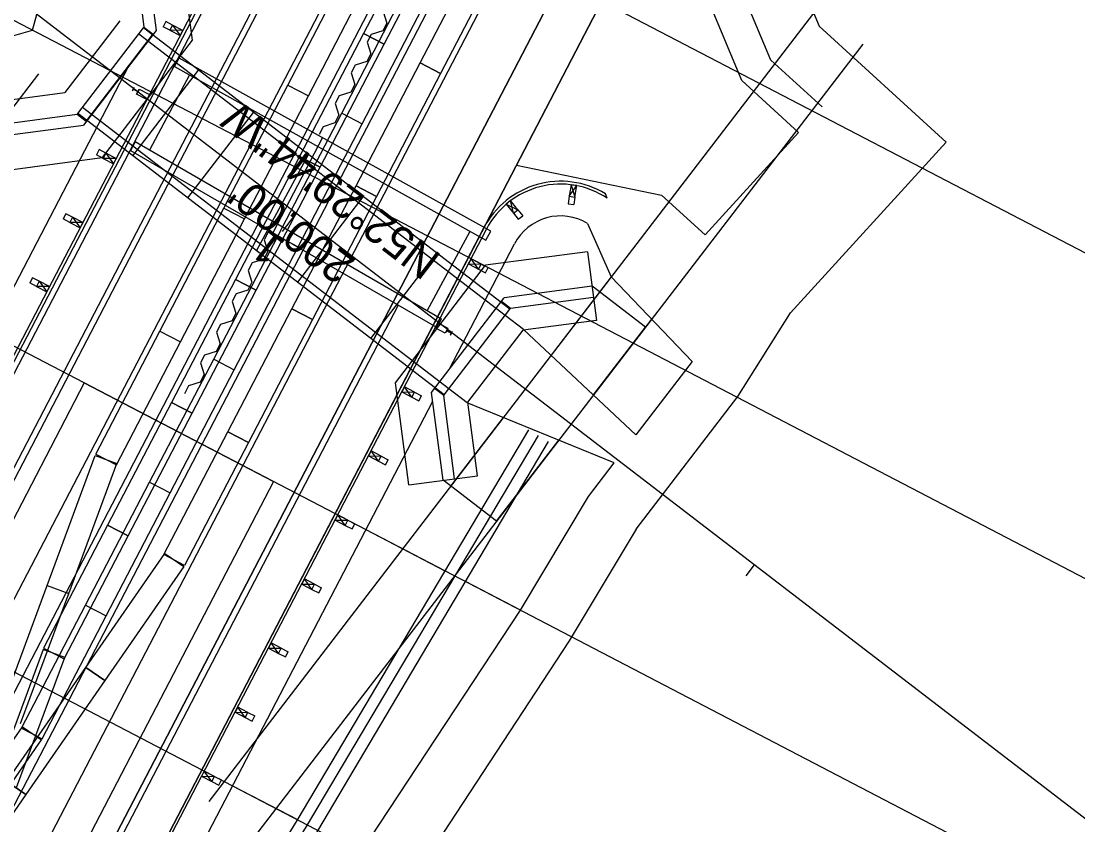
# Model space of a CAD drawing. Extents: x 2034057 to 2035954, y 247386 to 249135.
# Drawn here: x 2034212.3 to 2034303.8, y 247789 to 247858.5 of the extents above; entities that cross this region are included whole.
import ezdxf

# ---------------------------------------------------------------- set-up
doc = ezdxf.new("R2010")
doc.units = 0
for name, color, linetype in [('_CIVIL_CONSTRUCTION', 7, 'Continuous'), ('Default', 7, 'Continuous'), ('DR_X_Storm_Sewer', 7, 'Continuous'), ('DV_X_Property_Line', 7, 'Continuous'), ('GE_X_Alignment_1000_Curve_Data', 7, 'Continuous'), ('GE_X_Alignment_1000_Stations', 7, 'Continuous'), ('HY_X_Water_Edge', 7, 'Continuous'), ('PV_X_Driveway', 7, 'Continuous'), ('RD_X_Fence', 7, 'Continuous'), ('RD_X_GR_Lt', 7, 'Continuous'), ('RS_Raster1', 7, 'Continuous'), ('RW_X_CL_100_Cardinal_Points', 7, 'Continuous'), ('RW_X_Esmt_SH', 7, 'Continuous'), ('SC_Scratch1', 7, 'Continuous'), ('SN_X_Public', 7, 'Continuous'), ('SN_X_Text', 7, 'Continuous'), ('SV_Control_Point', 7, 'Continuous'), ('SV_P_Mon_Cells_Set', 7, 'Continuous'), ('SV_X_Break_Lines', 7, 'Continuous'), ('SV_X_Top_of_Bank', 7, 'Continuous'), ('UT_X_Telecom', 7, 'Continuous'), ('VG_X_Text', 7, 'Continuous'), ('XS_X_Ground_Line', 7, 'Continuous')]:
    doc.layers.add(name, color=color, linetype=linetype)

msp = doc.modelspace()

# ---------------------------------------------------------------- linework, layer by layer
at = {"layer": '_CIVIL_CONSTRUCTION'}
for p, q in [((2034315.483, 247781.011), (2034156.822, 247902.775)), ((2034281.239, 247859.578), (2034228.588, 247790.974)), ((2034285.205, 247856.534), (2034232.555, 247787.93))]:
    msp.add_line(p, q, dxfattribs=at)
at = {"layer": 'Default'}
for p, q in [((2034160.613, 247913.346), (2034338.015, 247820.997)), ((2034149.071, 247891.179), (2034326.466, 247798.816)), ((2034137.526, 247869.005), (2034314.921, 247776.641)), ((2034125.98, 247846.83), (2034303.375, 247754.467))]:
    msp.add_line(p, q, dxfattribs=at)
at = {"layer": 'DR_X_Storm_Sewer'}
for p, q in [((2034277.243, 247855.142), (2034271.022, 247870.084)), ((2034277.243, 247855.142), (2034281.68, 247851.086)), ((2034221.609, 247854.561), (2034190.6, 247795.005)), ((2034210.536, 247849.577), (2034213.884, 247853.94)), ((2034261.377, 247841.011), (2034263.431, 247836.375)), ((2034249.396, 247828.353), (2034255.062, 247839.235)), ((2034263.431, 247836.375), (2034258.225, 247829.592)), ((2034270.426, 247829.065), (2034263.431, 247836.375)), ((2034266.929, 247832.72), (2034261.892, 247826.156)), ((2034270.426, 247829.065), (2034265.558, 247822.721)), ((2034208.787, 247750.357), (2034247.981, 247825.635)), ((2034249.631, 247818.393), (2034254.091, 247824.205)), ((2034261.452, 247817.371), (2034263.69, 247820.287)), ((2034242.189, 247814.51), (2034249.026, 247810.95)), ((2034255.564, 247807.546), (2034250.803, 247810.025)), ((2034230.643, 247792.336), (2034236.256, 247789.414))]:
    msp.add_line(p, q, dxfattribs=at)
for points in [[(2034256.26, 247823.151), (2034236.288, 247789.466), (2034223.216, 247768.065), (2034211.274, 247746.04), (2034200.52, 247723.551), (2034200.47, 247723.489)], [(2034257.98, 247822.131), (2034238.002, 247788.435), (2034224.95, 247767.067), (2034213.056, 247745.131), (2034202.261, 247722.557)], [(2034228.624, 247765.202), (2034241.766, 247786.545), (2034255.564, 247807.546), (2034261.452, 247817.371)]]:
    msp.add_lwpolyline(points, dxfattribs=at)
msp.add_arc((2034259.053, 247837.157), 4.5, 58.91768, 152.49557, dxfattribs=at)
at = {"layer": 'DV_X_Property_Line'}
for p, q in [((2034235.313, 247874.384), (2034186.854, 247781.313)), ((2034262.587, 247860.183), (2034214.128, 247767.112))]:
    msp.add_line(p, q, dxfattribs=at)
at = {"layer": 'GE_X_Alignment_1000_Curve_Data'}
for p, q in [((2034236.152, 247841.893), (2034234.935, 247840.306)), ((2034275.818, 247811.452), (2034275.087, 247810.5))]:
    msp.add_line(p, q, dxfattribs=at)
at = {"layer": 'HY_X_Water_Edge'}
for p, q in [((2034266.395, 247832.024), (2034261.77, 247835.574)), ((2034261.892, 247826.156), (2034266.395, 247832.024)), ((2034253.508, 247815.232), (2034258.891, 247822.246)), ((2034253.508, 247815.232), (2034248.883, 247818.782))]:
    msp.add_line(p, q, dxfattribs=at)
at = {"layer": 'PV_X_Driveway'}
for p, q in [((2034183.71, 247766.074), (2034239.082, 247872.422)), ((2034247.065, 247868.265), (2034191.693, 247761.917))]:
    msp.add_line(p, q, dxfattribs=at)
for points in [[(2034243.772, 247856.528), (2034249.314, 247867.172), (2034247.54, 247868.095), (2034241.998, 247857.452)], [(2034238.231, 247845.884), (2034243.772, 247856.528), (2034241.998, 247857.452), (2034236.457, 247846.808)], [(2034232.689, 247835.241), (2034238.231, 247845.884), (2034236.457, 247846.808), (2034230.915, 247836.164)], [(2034227.147, 247824.597), (2034232.689, 247835.241), (2034230.915, 247836.164), (2034225.373, 247825.521)], [(2034221.605, 247813.953), (2034227.147, 247824.597), (2034225.373, 247825.521), (2034219.831, 247814.877)], [(2034216.063, 247803.31), (2034221.605, 247813.953), (2034219.831, 247814.877), (2034214.289, 247804.233)], [(2034211.946, 247792.171), (2034216.114, 247803.424), (2034214.239, 247804.119), (2034210.071, 247792.866)]]:
    msp.add_lwpolyline(points, close=True, dxfattribs=at)
at = {"layer": 'RD_X_Fence'}
for p, q in [((2034243.686, 247859.362), (2034244.006, 247858.351)), ((2034243.661, 247857.685), (2034242.65, 247857.365)), ((2034244.006, 247858.351), (2034243.661, 247857.685)), ((2034242.65, 247857.365), (2034242.304, 247856.7)), ((2034242.304, 247856.7), (2034242.624, 247855.689)), ((2034242.279, 247855.023), (2034241.267, 247854.703)), ((2034242.624, 247855.689), (2034242.279, 247855.023)), ((2034241.267, 247854.703), (2034240.922, 247854.037)), ((2034240.922, 247854.037), (2034241.242, 247853.026)), ((2034240.896, 247852.36), (2034239.885, 247852.04)), ((2034241.242, 247853.026), (2034240.896, 247852.36)), ((2034239.885, 247852.04), (2034239.54, 247851.375)), ((2034239.54, 247851.375), (2034239.86, 247850.363)), ((2034239.86, 247850.363), (2034239.514, 247849.698)), ((2034239.514, 247849.698), (2034238.503, 247849.378)), ((2034238.503, 247849.378), (2034238.157, 247848.712)), ((2034233.736, 247840.248), (2034233.391, 247839.582)), ((2034233.391, 247839.582), (2034233.711, 247838.571)), ((2034233.711, 247838.571), (2034233.365, 247837.906)), ((2034232.354, 247837.586), (2034232.009, 247836.92)), ((2034233.365, 247837.906), (2034232.354, 247837.586)), ((2034232.009, 247836.92), (2034232.329, 247835.909)), ((2034232.329, 247835.909), (2034231.983, 247835.243)), ((2034230.972, 247834.923), (2034230.626, 247834.257)), ((2034231.983, 247835.243), (2034230.972, 247834.923)), ((2034230.626, 247834.257), (2034230.946, 247833.246)), ((2034230.946, 247833.246), (2034230.601, 247832.58)), ((2034229.59, 247832.26), (2034229.244, 247831.595)), ((2034230.601, 247832.58), (2034229.59, 247832.26)), ((2034229.244, 247831.595), (2034229.564, 247830.583)), ((2034229.564, 247830.583), (2034229.219, 247829.918)), ((2034228.207, 247829.598), (2034227.862, 247828.932)), ((2034229.219, 247829.918), (2034228.207, 247829.598)), ((2034227.862, 247828.932), (2034228.182, 247827.921)), ((2034228.182, 247827.921), (2034227.836, 247827.255)), ((2034226.825, 247826.935), (2034226.48, 247826.269)), ((2034227.836, 247827.255), (2034226.825, 247826.935))]:
    msp.add_line(p, q, dxfattribs=at)
at = {"layer": 'RD_X_GR_Lt'}
for p, q in [((2034204.76, 247768.608), (2034254.604, 247864.34)), ((2034212.743, 247764.451), (2034262.587, 247860.183))]:
    msp.add_line(p, q, dxfattribs=at)
for points in [[(2034254.193, 247864.632), (2034248.651, 247853.988), (2034246.877, 247854.912), (2034252.419, 247865.555)], [(2034248.651, 247853.988), (2034243.109, 247843.344), (2034241.335, 247844.268), (2034246.877, 247854.912)], [(2034243.109, 247843.344), (2034237.567, 247832.701), (2034235.793, 247833.624), (2034241.335, 247844.268)], [(2034237.567, 247832.701), (2034232.025, 247822.057), (2034230.251, 247822.981), (2034235.793, 247833.624)], [(2034232.025, 247822.057), (2034226.484, 247811.413), (2034224.71, 247812.337), (2034230.251, 247822.981)], [(2034226.419, 247811.306), (2034219.59, 247801.439), (2034217.945, 247802.577), (2034224.774, 247812.444)], [(2034219.59, 247801.439), (2034212.761, 247791.571), (2034211.117, 247792.709), (2034217.945, 247802.577)], [(2034212.761, 247791.571), (2034205.932, 247781.704), (2034204.288, 247782.842), (2034211.117, 247792.709)]]:
    msp.add_lwpolyline(points, close=True, dxfattribs=at)
at = {"layer": 'RS_Raster1'}
for p, q in [((2034188.682, 247783.743), (2034235.756, 247874.153)), ((2034243.739, 247869.997), (2034196.665, 247779.587)), ((2034235.44, 247852.975), (2034240.981, 247863.618)), ((2034237.214, 247852.051), (2034242.755, 247862.695)), ((2034229.898, 247842.331), (2034235.44, 247852.975)), ((2034235.44, 247852.975), (2034237.214, 247852.051)), ((2034235.44, 247852.975), (2034237.214, 247852.051)), ((2034231.672, 247841.407), (2034237.214, 247852.051)), ((2034224.356, 247831.687), (2034229.898, 247842.331)), ((2034229.898, 247842.331), (2034231.672, 247841.407)), ((2034229.898, 247842.331), (2034231.672, 247841.407)), ((2034226.13, 247830.764), (2034231.672, 247841.407)), ((2034218.814, 247821.044), (2034224.356, 247831.687)), ((2034224.356, 247831.687), (2034226.13, 247830.764)), ((2034224.356, 247831.687), (2034226.13, 247830.764)), ((2034220.588, 247820.12), (2034226.13, 247830.764)), ((2034214.596, 247809.676), (2034218.763, 247820.929)), ((2034216.471, 247808.982), (2034220.639, 247820.234)), ((2034218.763, 247820.929), (2034220.639, 247820.234)), ((2034218.814, 247821.044), (2034220.588, 247820.12)), ((2034210.428, 247798.423), (2034214.596, 247809.676)), ((2034214.596, 247809.676), (2034216.471, 247808.982)), ((2034214.596, 247809.676), (2034216.471, 247808.982)), ((2034212.303, 247797.729), (2034216.471, 247808.982))]:
    msp.add_line(p, q, dxfattribs=at)
at = {"layer": 'RW_X_Esmt_SH'}
for p, q in [((2034239.526, 247872.191), (2034170.285, 247739.206)), ((2034259.039, 247862.031), (2034189.798, 247729.046)), ((2034217.797, 247827.21), (2034171.615, 247738.513)), ((2034217.797, 247827.21), (2034234.206, 247818.667)), ((2034234.206, 247818.667), (2034188.024, 247729.969))]:
    msp.add_line(p, q, dxfattribs=at)
at = {"layer": 'SC_Scratch1'}
for p, q in [((2034251.056, 247866.187), (2034192.77, 247754.241)), ((2034200.753, 247750.085), (2034259.039, 247862.031)), ((2034240.096, 247850.55), (2034245.638, 247861.194)), ((2034241.87, 247849.627), (2034247.412, 247860.27)), ((2034234.554, 247839.906), (2034240.096, 247850.55)), ((2034240.096, 247850.55), (2034241.87, 247849.627)), ((2034240.096, 247850.55), (2034241.87, 247849.627)), ((2034236.328, 247838.983), (2034241.87, 247849.627)), ((2034229.013, 247829.263), (2034234.554, 247839.906)), ((2034234.554, 247839.906), (2034236.328, 247838.983)), ((2034234.554, 247839.906), (2034236.328, 247838.983)), ((2034230.787, 247828.339), (2034236.328, 247838.983)), ((2034223.471, 247818.619), (2034229.013, 247829.263)), ((2034229.013, 247829.263), (2034230.787, 247828.339)), ((2034229.013, 247829.263), (2034230.787, 247828.339)), ((2034225.245, 247817.695), (2034230.787, 247828.339)), ((2034217.929, 247807.975), (2034223.471, 247818.619)), ((2034223.471, 247818.619), (2034225.245, 247817.695)), ((2034223.471, 247818.619), (2034225.245, 247817.695)), ((2034219.703, 247807.052), (2034225.245, 247817.695)), ((2034212.387, 247797.332), (2034217.929, 247807.975)), ((2034217.929, 247807.975), (2034219.703, 247807.052)), ((2034217.929, 247807.975), (2034219.703, 247807.052)), ((2034214.161, 247796.408), (2034219.703, 247807.052)), ((2034205.623, 247787.571), (2034212.452, 247797.439)), ((2034212.387, 247797.332), (2034214.161, 247796.408)), ((2034212.452, 247797.439), (2034214.096, 247796.301)), ((2034207.268, 247786.433), (2034214.096, 247796.301))]:
    msp.add_line(p, q, dxfattribs=at)
at = {"layer": 'SN_X_Public'}
msp.add_line((2034244.977, 247833.939), (2034190.242, 247728.815), dxfattribs=at)
at = {"layer": 'SN_X_Text'}
msp.add_line((2034194.19, 247852.248), (2034213.315, 247857.73), dxfattribs=at)
for points in [[(2034213.315, 247857.73), (2034220.149, 247882.354), (2034230.859, 247903.892), (2034241.703, 247925.386), (2034251.573, 247947.351), (2034261.177, 247969.46)], [(2034265.558, 247822.721), (2034255.842, 247831.824), (2034254.256, 247833.042)], [(2034263.69, 247820.287), (2034250.972, 247825.478), (2034249.385, 247826.696)]]:
    msp.add_lwpolyline(points, dxfattribs=at)
at = {"layer": 'SV_Control_Point'}
for p, q in [((2034259.798, 247843.367), (2034260.45, 247844.275)), ((2034259.956, 247844.354), (2034260.291, 247843.288)), ((2034259.798, 247843.367), (2034259.692, 247842.709)), ((2034260.291, 247843.288), (2034260.186, 247842.63)), ((2034263.089, 247843.18), (2034262.925, 247843.58)), ((2034254.333, 247842.665), (2034255.348, 247842.196)), ((2034254.957, 247841.884), (2034254.723, 247842.977)), ((2034255.348, 247842.196), (2034255.764, 247841.675)), ((2034259.692, 247842.709), (2034260.186, 247842.63)), ((2034254.957, 247841.884), (2034255.373, 247841.363)), ((2034255.373, 247841.363), (2034255.764, 247841.675)), ((2034206.219, 247751.923), (2034252.401, 247840.62)), ((2034206.441, 247751.807), (2034252.623, 247840.505)), ((2034251.951, 247837.049), (2034251.295, 247837.955)), ((2034251.064, 247837.511), (2034252.182, 247837.493)), ((2034251.951, 247837.049), (2034252.543, 247836.742)), ((2034252.182, 247837.493), (2034252.773, 247837.185)), ((2034252.543, 247836.742), (2034252.773, 247837.185)), ((2034249.105, 247831.582), (2034249.256, 247831.873)), ((2034249.105, 247831.582), (2034249.12, 247831.574)), ((2034249.12, 247831.574), (2034249.193, 247831.713)), ((2034249.193, 247831.713), (2034249.597, 247831.502)), ((2034249.199, 247831.726), (2034249.272, 247831.865)), ((2034249.199, 247831.726), (2034249.604, 247831.515)), ((2034249.256, 247831.873), (2034249.272, 247831.865)), ((2034249.525, 247831.363), (2034249.597, 247831.502)), ((2034249.525, 247831.363), (2034249.541, 247831.355)), ((2034249.541, 247831.355), (2034249.692, 247831.646)), ((2034249.604, 247831.515), (2034249.676, 247831.654)), ((2034249.676, 247831.654), (2034249.692, 247831.646)), ((2034246.179, 247825.962), (2034245.522, 247826.868)), ((2034245.292, 247826.424), (2034246.409, 247826.406)), ((2034246.179, 247825.962), (2034246.77, 247825.654)), ((2034246.409, 247826.406), (2034247.001, 247826.098)), ((2034246.77, 247825.654), (2034247.001, 247826.098)), ((2034243.292, 247820.419), (2034242.636, 247821.324)), ((2034242.405, 247820.88), (2034243.523, 247820.862)), ((2034243.292, 247820.419), (2034243.883, 247820.111)), ((2034243.523, 247820.862), (2034244.114, 247820.554)), ((2034243.883, 247820.111), (2034244.114, 247820.554)), ((2034240.406, 247814.875), (2034239.75, 247815.78)), ((2034239.519, 247815.337), (2034240.637, 247815.319)), ((2034240.406, 247814.875), (2034240.997, 247814.567)), ((2034240.637, 247815.319), (2034241.228, 247815.011)), ((2034240.997, 247814.567), (2034241.228, 247815.011)), ((2034237.519, 247809.331), (2034236.863, 247810.237)), ((2034236.632, 247809.793), (2034237.75, 247809.775)), ((2034237.519, 247809.331), (2034238.111, 247809.024)), ((2034237.75, 247809.775), (2034238.342, 247809.467)), ((2034238.111, 247809.024), (2034238.342, 247809.467)), ((2034234.633, 247803.788), (2034233.977, 247804.693)), ((2034233.746, 247804.25), (2034234.864, 247804.231)), ((2034234.633, 247803.788), (2034235.224, 247803.48)), ((2034234.864, 247804.231), (2034235.455, 247803.923)), ((2034235.224, 247803.48), (2034235.455, 247803.923)), ((2034231.747, 247798.244), (2034231.091, 247799.15)), ((2034230.86, 247798.706), (2034231.978, 247798.688)), ((2034231.747, 247798.244), (2034232.338, 247797.936)), ((2034231.978, 247798.688), (2034232.569, 247798.38)), ((2034232.338, 247797.936), (2034232.569, 247798.38)), ((2034227.973, 247793.162), (2034229.091, 247793.144)), ((2034228.86, 247792.701), (2034228.204, 247793.606)), ((2034228.86, 247792.701), (2034229.452, 247792.393)), ((2034229.091, 247793.144), (2034229.683, 247792.836)), ((2034229.452, 247792.393), (2034229.683, 247792.836))]:
    msp.add_line(p, q, dxfattribs=at)
for points in [[(2034260.291, 247843.288), (2034260.45, 247844.275), (2034259.956, 247844.354), (2034259.798, 247843.367)], [(2034255.348, 247842.196), (2034254.723, 247842.977), (2034254.333, 247842.665), (2034254.957, 247841.884)], [(2034252.182, 247837.493), (2034251.295, 247837.955), (2034251.064, 247837.511), (2034251.951, 247837.049)], [(2034249.296, 247831.949), (2034249.065, 247831.506), (2034248.178, 247831.968), (2034248.409, 247832.411)], [(2034246.409, 247826.406), (2034245.522, 247826.868), (2034245.292, 247826.424), (2034246.179, 247825.962)], [(2034243.523, 247820.862), (2034242.636, 247821.324), (2034242.405, 247820.88), (2034243.292, 247820.419)], [(2034240.637, 247815.319), (2034239.75, 247815.78), (2034239.519, 247815.337), (2034240.406, 247814.875)], [(2034237.75, 247809.775), (2034236.863, 247810.237), (2034236.632, 247809.793), (2034237.519, 247809.331)], [(2034234.864, 247804.231), (2034233.977, 247804.693), (2034233.746, 247804.25), (2034234.633, 247803.788)], [(2034231.978, 247798.688), (2034231.091, 247799.15), (2034230.86, 247798.706), (2034231.747, 247798.244)], [(2034229.091, 247793.144), (2034228.204, 247793.606), (2034227.973, 247793.162), (2034228.86, 247792.701)]]:
    msp.add_lwpolyline(points, close=True, dxfattribs=at)
for radius, start in [(7.5, 58.91768), (7.25, 56.17942)]:
    msp.add_arc((2034259.053, 247837.157), radius, start, 152.49557, dxfattribs=at)
at = {"layer": 'SV_P_Mon_Cells_Set'}
for p, q in [((2034192.977, 247793.616), (2034235.091, 247874.5)), ((2034235.313, 247874.384), (2034193.199, 247793.5)), ((2034224.87, 247858.478), (2034224.639, 247858.035)), ((2034225.23, 247857.727), (2034224.639, 247858.035)), ((2034225.461, 247858.17), (2034224.87, 247858.478)), ((2034226.348, 247857.708), (2034225.23, 247857.727)), ((2034225.461, 247858.17), (2034226.117, 247857.265)), ((2034222.099, 247852.777), (2034221.947, 247852.486)), ((2034221.963, 247852.478), (2034221.947, 247852.486)), ((2034222.036, 247852.617), (2034221.963, 247852.478)), ((2034222.44, 247852.407), (2034222.036, 247852.617)), ((2034222.115, 247852.769), (2034222.042, 247852.63)), ((2034222.447, 247852.419), (2034222.042, 247852.63)), ((2034222.115, 247852.769), (2034222.099, 247852.777)), ((2034222.44, 247852.407), (2034222.368, 247852.267)), ((2034222.383, 247852.259), (2034222.368, 247852.267)), ((2034222.535, 247852.55), (2034222.383, 247852.259)), ((2034222.519, 247852.559), (2034222.447, 247852.419)), ((2034222.535, 247852.55), (2034222.519, 247852.559)), ((2034219.097, 247847.391), (2034218.866, 247846.947)), ((2034219.457, 247846.639), (2034218.866, 247846.947)), ((2034219.688, 247847.083), (2034219.097, 247847.391)), ((2034219.688, 247847.083), (2034220.344, 247846.178)), ((2034220.575, 247846.621), (2034219.457, 247846.639)), ((2034216.211, 247841.847), (2034215.98, 247841.404)), ((2034216.571, 247841.096), (2034215.98, 247841.404)), ((2034216.802, 247841.539), (2034216.211, 247841.847)), ((2034216.802, 247841.539), (2034217.458, 247840.634)), ((2034217.689, 247841.078), (2034216.571, 247841.096)), ((2034213.324, 247836.304), (2034213.093, 247835.86)), ((2034213.685, 247835.552), (2034213.093, 247835.86)), ((2034213.916, 247835.996), (2034213.324, 247836.304)), ((2034213.916, 247835.996), (2034214.572, 247835.09)), ((2034214.803, 247835.534), (2034213.685, 247835.552))]:
    msp.add_line(p, q, dxfattribs=at)
for points in [[(2034225.23, 247857.727), (2034226.117, 247857.265), (2034226.348, 247857.708), (2034225.461, 247858.17)], [(2034222.344, 247852.183), (2034222.575, 247852.627), (2034223.462, 247852.165), (2034223.231, 247851.721)], [(2034219.457, 247846.639), (2034220.344, 247846.178), (2034220.575, 247846.621), (2034219.688, 247847.083)], [(2034216.571, 247841.096), (2034217.458, 247840.634), (2034217.689, 247841.078), (2034216.802, 247841.539)], [(2034213.685, 247835.552), (2034214.572, 247835.09), (2034214.803, 247835.534), (2034213.916, 247835.996)]]:
    msp.add_lwpolyline(points, close=True, dxfattribs=at)
at = {"layer": 'SV_X_Break_Lines'}
msp.add_lwpolyline([(2034191.465, 247710.484), (2034201.373, 247723.019), (2034212.165, 247745.586), (2034224.083, 247767.566), (2034237.145, 247788.951), (2034257.12, 247822.641)], dxfattribs=at)
at = {"layer": 'SV_X_Top_of_Bank'}
for p, q in [((2034222.034, 247865.178), (2034222.98, 247857.99)), ((2034223.026, 247865.308), (2034224.025, 247857.71)), ((2034226, 247865.7), (2034227.162, 247856.869)), ((2034220.889, 247858.55), (2034216.114, 247852.328)), ((2034217.247, 247850.52), (2034222.929, 247857.924)), ((2034224.025, 247857.71), (2034217.737, 247849.516)), ((2034222.98, 247857.99), (2034222.929, 247857.924)), ((2034254.661, 247833.571), (2034222.929, 247857.924)), ((2034222.98, 247857.99), (2034223.773, 247857.381)), ((2034218.04, 247849.911), (2034223.722, 247857.315)), ((2034227.162, 247856.869), (2034219.361, 247846.704)), ((2034254.256, 247833.042), (2034222.523, 247857.395)), ((2034222.007, 247846.867), (2034227.689, 247854.271)), ((2034209.747, 247851.491), (2034216.114, 247852.328)), ((2034210.008, 247849.508), (2034217.196, 247850.453)), ((2034217.247, 247850.52), (2034217.196, 247850.453)), ((2034217.196, 247850.453), (2034217.989, 247849.845)), ((2034248.979, 247826.167), (2034217.247, 247850.52)), ((2034249.385, 247826.696), (2034217.653, 247851.048)), ((2034226.766, 247843.214), (2034232.449, 247850.618)), ((2034210.138, 247848.516), (2034217.737, 247849.516)), ((2034210.53, 247845.542), (2034219.361, 247846.704)), ((2034232.716, 247838.648), (2034237.209, 247846.965)), ((2034236.286, 247835.908), (2034241.968, 247843.312)), ((2034242.633, 247831.037), (2034248.315, 247838.441)), ((2034261.378, 247838.549), (2034252.548, 247837.387)), ((2034261.378, 247838.549), (2034262.161, 247832.6)), ((2034244.746, 247827.221), (2034252.548, 247837.387)), ((2034261.77, 247835.574), (2034254.171, 247834.574)), ((2034247.883, 247826.381), (2034254.171, 247834.574)), ((2034254.712, 247833.637), (2034253.919, 247834.246)), ((2034261.9, 247834.583), (2034254.712, 247833.637)), ((2034248.979, 247826.167), (2034254.661, 247833.571)), ((2034254.661, 247833.571), (2034254.712, 247833.637)), ((2034262.161, 247832.6), (2034255.794, 247831.762)), ((2034251.019, 247825.54), (2034255.794, 247831.762)), ((2034245.908, 247818.391), (2034244.746, 247827.221)), ((2034248.928, 247826.101), (2034248.135, 247826.709)), ((2034248.883, 247818.782), (2034247.883, 247826.381)), ((2034248.928, 247826.101), (2034248.979, 247826.167)), ((2034249.874, 247818.913), (2034248.928, 247826.101)), ((2034251.857, 247819.173), (2034251.019, 247825.54)), ((2034245.908, 247818.391), (2034251.857, 247819.173))]:
    msp.add_line(p, q, dxfattribs=at)
for points in [[(2034223.722, 247857.315), (2034222.929, 247857.924), (2034222.98, 247857.99), (2034223.773, 247857.381)], [(2034217.989, 247849.845), (2034217.196, 247850.453), (2034217.247, 247850.52), (2034218.04, 247849.911)], [(2034253.919, 247834.246), (2034254.712, 247833.637), (2034254.661, 247833.571), (2034253.868, 247834.18)], [(2034248.186, 247826.775), (2034248.979, 247826.167), (2034248.928, 247826.101), (2034248.135, 247826.709)]]:
    msp.add_lwpolyline(points, close=True, dxfattribs=at)
at = {"layer": 'UT_X_Telecom'}
for p, q in [((2034225.633, 247854.58), (2034226.033, 247855.306)), ((2034253.011, 247840.338), (2034226.033, 247855.306)), ((2034225.633, 247854.58), (2034252.586, 247839.571)), ((2034226.909, 247853.87), (2034223.464, 247847.357)), ((2034222.231, 247848.07), (2034221.82, 247847.314)), ((2034248.742, 247832.73), (2034222.231, 247848.07)), ((2034238.428, 247848.429), (2034234.142, 247840.197)), ((2034221.82, 247847.314), (2034248.307, 247832.016)), ((2034247.505, 247833.445), (2034251.214, 247840.335)), ((2034252.586, 247839.571), (2034253.011, 247840.338)), ((2034248.307, 247832.016), (2034248.742, 247832.73))]:
    msp.add_line(p, q, dxfattribs=at)
at = {"layer": 'VG_X_Text'}
for p, q in [((2034274.729, 247853.375), (2034267.723, 247870.203)), ((2034274.729, 247853.375), (2034279.656, 247848.871)), ((2034271.559, 247840.015), (2034279.656, 247848.871)), ((2034255.23, 247846.053), (2034267.793, 247843.458)), ((2034267.793, 247843.458), (2034271.559, 247840.015))]:
    msp.add_line(p, q, dxfattribs=at)
at = {"layer": 'XS_X_Ground_Line'}
for points in [[(2034306.53, 247924.887), (2034297.915, 247900.234), (2034286.009, 247876.887), (2034278.747, 247864.538), (2034281.434, 247858.085), (2034292.434, 247848.028)], [(2034265.594, 247814.555), (2034274.393, 247826.021), (2034278.939, 247833.267), (2034292.434, 247848.028)], [(2034265.594, 247814.555), (2034259.8, 247804.887), (2034245.985, 247783.861), (2034232.878, 247762.574)]]:
    msp.add_lwpolyline(points, dxfattribs=at)

# ---------------------------------------------------------------- texts
at = {"layer": 'GE_X_Alignment_1000_Curve_Data'}
msp.add_text('1', height=2.8, rotation=142.49557, dxfattribs=at).set_placement((2034235.357, 247839.352))
at = {"layer": 'GE_X_Alignment_1000_Stations'}
msp.add_text("200.00'", height=2.8, rotation=142.49557, dxfattribs=at).set_placement((2034241.426, 247837.793))
at = {"layer": 'RW_X_CL_100_Cardinal_Points'}
msp.add_text('N52°29\'44"W', height=2.8, rotation=142.49557, dxfattribs=at).set_placement((2034248.844, 247838.203))

doc.saveas('drawing.dxf')
